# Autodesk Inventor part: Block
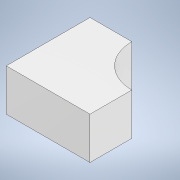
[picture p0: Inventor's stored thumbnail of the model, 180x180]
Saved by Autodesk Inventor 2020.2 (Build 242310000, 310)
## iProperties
Created: 2020-01
Part Number: Block
Material: PBT Plastic
Document SubType Name: Modeling
Designer: thira
Density: 1.31 g/cm^3
Appearance: Smooth - White
Author: thira
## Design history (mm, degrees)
sketch "Sketch1"
  geometry: L1 (0, 0)-(0, -20); L2 (0, -20)-(-10, -20); L3 (-20, -10)-(-20, 0); L4 (0, 0)-(-20, 0); A1 r 10 centre (-20, -20) between (-10, -20) and (-20, -10)
  constraints: 8 end point, 2 horizontal, 2 perpendicular, 2 point on circle, 1 centre point, 1 point on line, 1 vertical
  dimensions: "d0" = 20 distance of L1.start L1.end; "d1" = 10 distance of L1.end L2.end; "d3" = 20 distance of L1.start L3.end
extrude "Extrusion1" new body sketch "Sketch1" distance "d4" = 10; taper "d5" = 0 deg
body "Solid1"
